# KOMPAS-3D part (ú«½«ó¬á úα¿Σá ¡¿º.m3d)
File: created 24.10.2015 22:02:07, last saved 06.04.2016 12:41:15.
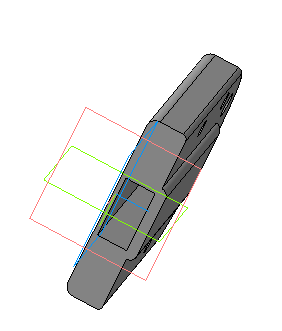
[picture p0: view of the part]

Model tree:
1. Эскиз:1
2. Операция выдавливания:1
     Расстояние 1 = 16
3. Эскиз:11
     Толщина стенки 1 = 2; Толщина стенки 2 = 6; Расстояние 1 = 10; Расстояние 2 = 3
4. Скругление:9
     Радиус = 4
5. Скругление:10
     Радиус = 2
6. Эскиз:12
7. Операция выдавливания:8
     Толщина стенки 1 = 2; Толщина стенки 2 = 6; Расстояние 1 = 15; Расстояние 2 = 3
8. Эскиз:13
9. Операция выдавливания:9
     Толщина стенки 1 = 2; Толщина стенки 2 = 6; Расстояние 1 = 0.5; Расстояние 2 = 3
10. Эскиз:14
11. Вырезать элемент выдавливания:5
     Толщина стенки 2 = 1.5; Расстояние 1 = 22.6
12. Скругление:11
     Радиус = 2
13. Эскиз:15
14. Вырезать элемент выдавливания:6
     Толщина стенки 2 = 1.5; Расстояние 1 = 112.6
15. Эскиз:16
16. Операция выдавливания:10
     Расстояние 1 = 16; Расстояние 2 = 96.2519
17. Скругление:12
     Радиус = 3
